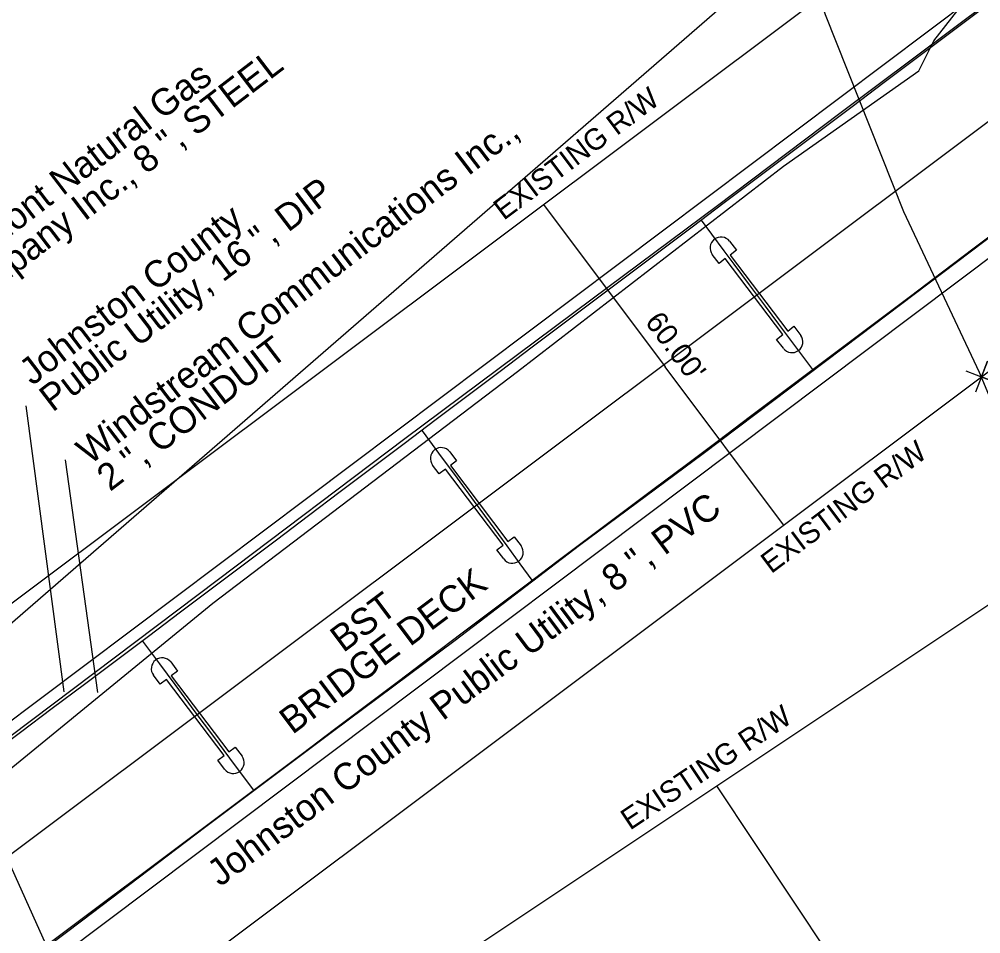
# Model space of a CAD drawing. Extents: x 2186615 to 2188822, y 629899 to 631820.
# Drawn here: x 2187648.6 to 2187792.7, y 630749.3 to 630886.3 of the extents above; entities that cross this region are included whole.
import ezdxf

# ---------------------------------------------------------------- set-up
doc = ezdxf.new("R2010")
doc.units = 0
for name, color, linetype in [('Exist Horizontal Alignment', 7, 'Continuous'), ('Exist Hydro Jurisdictional Stream or Body of Water', 7, 'Continuous'), ('Exist Other Culture Area Outline', 7, 'Continuous'), ('Exist Property Corner CELL', 7, 'Continuous'), ('Exist Right of Way Line', 7, 'Continuous'), ('Exist Right of Way Line Text', 7, 'Continuous'), ('Exist Right of Way Width CELL', 7, 'Continuous'), ('Exist Structure Major Bridge Seam', 7, 'Continuous'), ('Exist Structure Major Deck Tunnel Box Culvert', 7, 'Continuous'), ('Exist Structure Major Deck Tunnel Box Culvert Text', 7, 'Continuous'), ('Exist Utilities Gas UG Line SUE LOS C', 7, 'Continuous'), ('Exist Utilities Gas UG Line SUE LOS C Text', 7, 'Continuous'), ('Exist Utilities Sanitary Sewer Forced Main SUE LOS B', 7, 'Continuous'), ('Exist Utilities Sanitary Sewer Forced Main SUE LOS B Text', 7, 'Continuous'), ('Exist Utilities Telephone UG FO SUE LOS B', 7, 'Continuous'), ('Exist Utilities Telephone UG FO SUE LOS B Leader', 7, 'Continuous'), ('Exist Utilities Telephone UG FO SUE LOS B Text', 7, 'Continuous'), ('Exist Utilities Water UG Line SUE LOS B', 7, 'Continuous'), ('Exist Utilities Water UG Line SUE LOS B Leader', 7, 'Continuous'), ('Exist Utilities Water UG Line SUE LOS B Text', 7, 'Continuous')]:
    doc.layers.add(name, color=color, linetype=linetype)

msp = doc.modelspace()

# ---------------------------------------------------------------- linework, layer by layer
at = {"layer": 'Exist Horizontal Alignment'}
msp.add_line((2187136.41, 630378.11), (2188520.86, 631416.04), dxfattribs=at)
at = {"layer": 'Exist Hydro Jurisdictional Stream or Body of Water'}
for points in [[(2187808.69, 630794.71), (2187792.54, 630833.36), (2187781.22, 630857.42), (2187769.44, 630886.96), (2187764.08, 630902.91), (2187764.77, 630914.18), (2187760.54, 630924.3)], [(2187685.21, 630670.03), (2187676.46, 630688.92), (2187667.73, 630709.8), (2187657.08, 630737.8), (2187643.12, 630768.72), (2187641.56, 630778.99)]]:
    msp.add_lwpolyline(points, dxfattribs=at)
at = {"layer": 'Exist Other Culture Area Outline'}
for p, q in [((2187755.08, 630853.04), (2187756.11, 630851.68)), ((2187753.51, 630849.71), (2187752.5, 630851.04)), ((2187756.11, 630851.68), (2187755.17, 630850.96)), ((2187755.17, 630850.96), (2187763.8, 630839.57)), ((2187754.45, 630850.42), (2187753.51, 630849.71)), ((2187763.09, 630839.03), (2187754.45, 630850.42)), ((2187763.8, 630839.57), (2187764.74, 630840.28)), ((2187764.74, 630840.28), (2187765.77, 630838.92)), ((2187762.14, 630838.31), (2187763.09, 630839.03)), ((2187763.16, 630836.98), (2187762.14, 630838.31)), ((2187713.16, 630821.48), (2187714.19, 630820.12)), ((2187711.59, 630818.15), (2187710.58, 630819.49)), ((2187714.19, 630820.12), (2187713.25, 630819.41)), ((2187713.25, 630819.41), (2187721.88, 630808.01)), ((2187712.53, 630818.87), (2187711.59, 630818.15)), ((2187721.17, 630807.47), (2187712.53, 630818.87)), ((2187721.88, 630808.01), (2187722.82, 630808.72)), ((2187722.82, 630808.72), (2187723.85, 630807.37)), ((2187720.22, 630806.76), (2187721.17, 630807.47)), ((2187721.24, 630805.42), (2187720.22, 630806.76)), ((2187671.35, 630789.98), (2187672.38, 630788.62)), ((2187669.78, 630786.65), (2187668.76, 630787.98)), ((2187670.72, 630787.36), (2187669.78, 630786.65)), ((2187679.35, 630775.96), (2187670.72, 630787.36)), ((2187672.38, 630788.62), (2187671.43, 630787.9)), ((2187671.43, 630787.9), (2187680.07, 630776.51)), ((2187678.41, 630775.25), (2187679.35, 630775.96)), ((2187680.07, 630776.51), (2187681.01, 630777.22)), ((2187681.01, 630777.22), (2187682.04, 630775.86)), ((2187679.42, 630773.92), (2187678.41, 630775.25))]:
    msp.add_line(p, q, dxfattribs=at)
for centre, start, end in [((2187753.8, 630852.03), 38.2035, 217.1439), ((2187764.45, 630837.96), 217.1439, 36.0842), ((2187711.88, 630820.47), 38.2035, 217.1439), ((2187722.54, 630806.4), 217.1439, 36.0842), ((2187670.06, 630788.97), 38.2035, 217.1439), ((2187680.72, 630774.9), 217.1439, 36.0842)]:
    msp.add_arc(centre, 1.63, start, end, dxfattribs=at)
at = {"layer": 'Exist Property Corner CELL'}
msp.add_lwpolyline([(2187790.48, 630833.63), (2187795.15, 630831.83), (2187792.82, 630832.73), (2187793.72, 630835.06), (2187791.92, 630830.4)], dxfattribs=at)
at = {"layer": 'Exist Right of Way Line'}
for p, q in [((2187118.41, 630402.11), (2188502.83, 631440.02)), ((2187154.4, 630354.1), (2188538.85, 631392.04)), ((2187522.53, 630617.66), (2187850.44, 630836.28))]:
    msp.add_line(p, q, dxfattribs=at)
at = {"layer": 'Exist Right of Way Width CELL'}
for p, q in [((2187727.2, 630858.53), (2187745.42, 630834.22)), ((2187763.19, 630810.52), (2187745.42, 630834.22)), ((2187753.12, 630771.4), (2187785.63, 630722.64))]:
    msp.add_line(p, q, dxfattribs=at)
at = {"layer": 'Exist Structure Major Bridge Seam'}
for points in [[(2187750.82, 630856.17), (2187752.37, 630854.08), (2187754.23, 630851.6), (2187755.72, 630849.59), (2187758.03, 630846.51), (2187760.43, 630843.29), (2187762.42, 630840.62), (2187765.12, 630837.01), (2187767.49, 630833.83)], [(2187709.03, 630824.63), (2187711.49, 630821.27), (2187714.26, 630817.5), (2187716.82, 630814.01), (2187719.2, 630810.77), (2187721.69, 630807.37), (2187723.67, 630804.67), (2187725.44, 630802.26)], [(2187667.11, 630793.12), (2187669.67, 630789.68), (2187671.96, 630786.59), (2187674.98, 630782.53), (2187677.76, 630778.8), (2187680.16, 630775.57), (2187682.05, 630773.02), (2187683.73, 630770.76)]]:
    msp.add_lwpolyline(points, dxfattribs=at)
at = {"layer": 'Exist Structure Major Deck Tunnel Box Culvert'}
for p, q in [((2187582.05, 630732.05), (2187832.7, 630920.52)), ((2187852.33, 630894.37), (2187601.73, 630705.99))]:
    msp.add_line(p, q, dxfattribs=at)
for points in [[(2187644.01, 630775.86), (2187648.81, 630779.46), (2187653.6, 630783.06), (2187658.4, 630786.66), (2187663.2, 630790.27), (2187668, 630793.87), (2187672.8, 630797.47), (2187677.59, 630801.08), (2187682.38, 630804.69), (2187687.18, 630808.3), (2187691.97, 630811.91), (2187696.76, 630815.52), (2187701.55, 630819.12), (2187706.35, 630822.74), (2187711.14, 630826.35), (2187715.93, 630829.96), (2187720.72, 630833.57), (2187725.51, 630837.18), (2187730.3, 630840.79), (2187735.1, 630844.4), (2187739.9, 630848), (2187744.69, 630851.61), (2187749.49, 630855.21), (2187754.29, 630858.81), (2187759.09, 630862.41), (2187763.88, 630866.02), (2187768.68, 630869.62), (2187773.47, 630873.23), (2187778.26, 630876.85), (2187783.05, 630880.46), (2187787.85, 630884.07), (2187792.64, 630887.67)], [(2187796.56, 630855.6), (2187791.76, 630852), (2187786.97, 630848.39), (2187782.18, 630844.77), (2187777.39, 630841.16), (2187772.6, 630837.55), (2187767.8, 630833.95), (2187763, 630830.34), (2187758.21, 630826.74), (2187753.41, 630823.13), (2187748.61, 630819.53), (2187743.81, 630815.93), (2187739.01, 630812.33), (2187734.22, 630808.72), (2187729.42, 630805.12), (2187724.62, 630801.51), (2187719.83, 630797.91), (2187715.04, 630794.3), (2187710.25, 630790.69), (2187705.46, 630787.07), (2187700.67, 630783.46), (2187695.87, 630779.85), (2187691.08, 630776.24), (2187686.29, 630772.63), (2187681.49, 630769.03), (2187676.69, 630765.43), (2187671.89, 630761.83), (2187667.09, 630758.23), (2187662.29, 630754.63), (2187657.49, 630751.03), (2187652.69, 630747.43)]]:
    msp.add_lwpolyline(points, dxfattribs=at)
at = {"layer": 'Exist Utilities Gas UG Line SUE LOS C'}
msp.add_line((2187633.26, 630783.47), (2187773.44, 630905.16), dxfattribs=at)
at = {"layer": 'Exist Utilities Sanitary Sewer Forced Main SUE LOS B'}
msp.add_lwpolyline([(2187639.4, 630737.18), (2187658.16, 630751.34), (2187676.41, 630765.17), (2187695.58, 630779.55), (2187713.95, 630793.24), (2187732.6, 630807.47), (2187751.11, 630821.21), (2187774.55, 630838.89), (2187793.19, 630853.01), (2187817.13, 630870.75), (2187832.54, 630882.73), (2187848.61, 630894.45), (2187859.56, 630897.68), (2187872.29, 630907.08), (2187904.19, 630928.23), (2187917.85, 630937.14), (2187951.64, 630961.53), (2187983.48, 630985.87), (2188013.42, 631007.09), (2188037.93, 631025.04), (2188052.05, 631035.58)], dxfattribs=at)
at = {"layer": 'Exist Utilities Telephone UG FO SUE LOS B'}
for points in [[(2187785.72, 630883.08), (2187793.24, 630892.77), (2187804.79, 630906.92), (2187826.49, 630925.65), (2187859.07, 630951.55)], [(2187635.53, 630764.37), (2187677.66, 630798.79), (2187723.32, 630833.53), (2187763.18, 630864.29), (2187783.47, 630878.54), (2187785.72, 630883.08)]]:
    msp.add_lwpolyline(points, dxfattribs=at)
at = {"layer": 'Exist Utilities Telephone UG FO SUE LOS B Leader'}
msp.add_line((2187660.43, 630785.39), (2187655.58, 630820.27), dxfattribs=at)
at = {"layer": 'Exist Utilities Water UG Line SUE LOS B'}
msp.add_lwpolyline([(2187641.11, 630774.22), (2187678.52, 630802.38), (2187706.44, 630823.47), (2187734.48, 630844.42), (2187753.27, 630858.4), (2187771.59, 630872.2), (2187805.1, 630897.31), (2187825.65, 630912.81), (2187836.42, 630921.29)], dxfattribs=at)
at = {"layer": 'Exist Utilities Water UG Line SUE LOS B Leader'}
msp.add_line((2187655.4, 630785.52), (2187649.7, 630828.36), dxfattribs=at)

# ---------------------------------------------------------------- texts
at = {"layer": 'Exist Right of Way Line Text'}
for rotation, p in [(36.8593, (2187721.25, 630856.07)), (36.8593, (2187761.32, 630803.12)), (33.6919, (2187740.17, 630764.69))]:
    msp.add_text('EXISTING R/W', height=3.2, rotation=rotation, dxfattribs=at).set_placement(p)
at = {"layer": 'Exist Right of Way Width CELL'}
msp.add_text("60.00'", height=3.2, rotation=306.8593, dxfattribs=at).set_placement((2187742.3, 630840.93))
at = {"layer": 'Exist Structure Major Deck Tunnel Box Culvert Text'}
for s, p in [('BRIDGE DECK', (2187689.58, 630779.02)), ('BST ', (2187697.2, 630791.28))]:
    msp.add_text(s, height=4, rotation=36.8288, dxfattribs=at).set_placement(p)
at = {"layer": 'Exist Utilities Gas UG Line SUE LOS C Text'}
for s, p in [('Company Inc., 8 ", STEEL', (2187639.06, 630841.15)), ('Piedmont Natural Gas', (2187636.02, 630845.13))]:
    msp.add_text(s, height=4, rotation=37.3672, dxfattribs=at).set_placement(p)
at = {"layer": 'Exist Utilities Sanitary Sewer Forced Main SUE LOS B Text'}
msp.add_text('Johnston County Public Utility, 8 ", PVC', height=4, rotation=36.7067, dxfattribs=at).set_placement((2187678.74, 630756.21))
at = {"layer": 'Exist Utilities Telephone UG FO SUE LOS B Text'}
for s, p in [('Windstream Communications Inc.,', (2187659.21, 630819.42)), ('2 ", CONDUIT', (2187662.25, 630815.44))]:
    msp.add_text(s, height=4, rotation=37.3672, dxfattribs=at).set_placement(p)
at = {"layer": 'Exist Utilities Water UG Line SUE LOS B Text'}
for s, p in [('Public Utility, 16 ", DIP', (2187653.64, 630827.32)), ('Johnston County ', (2187650.6, 630831.3))]:
    msp.add_text(s, height=4, rotation=37.3672, dxfattribs=at).set_placement(p)

doc.saveas('drawing.dxf')
